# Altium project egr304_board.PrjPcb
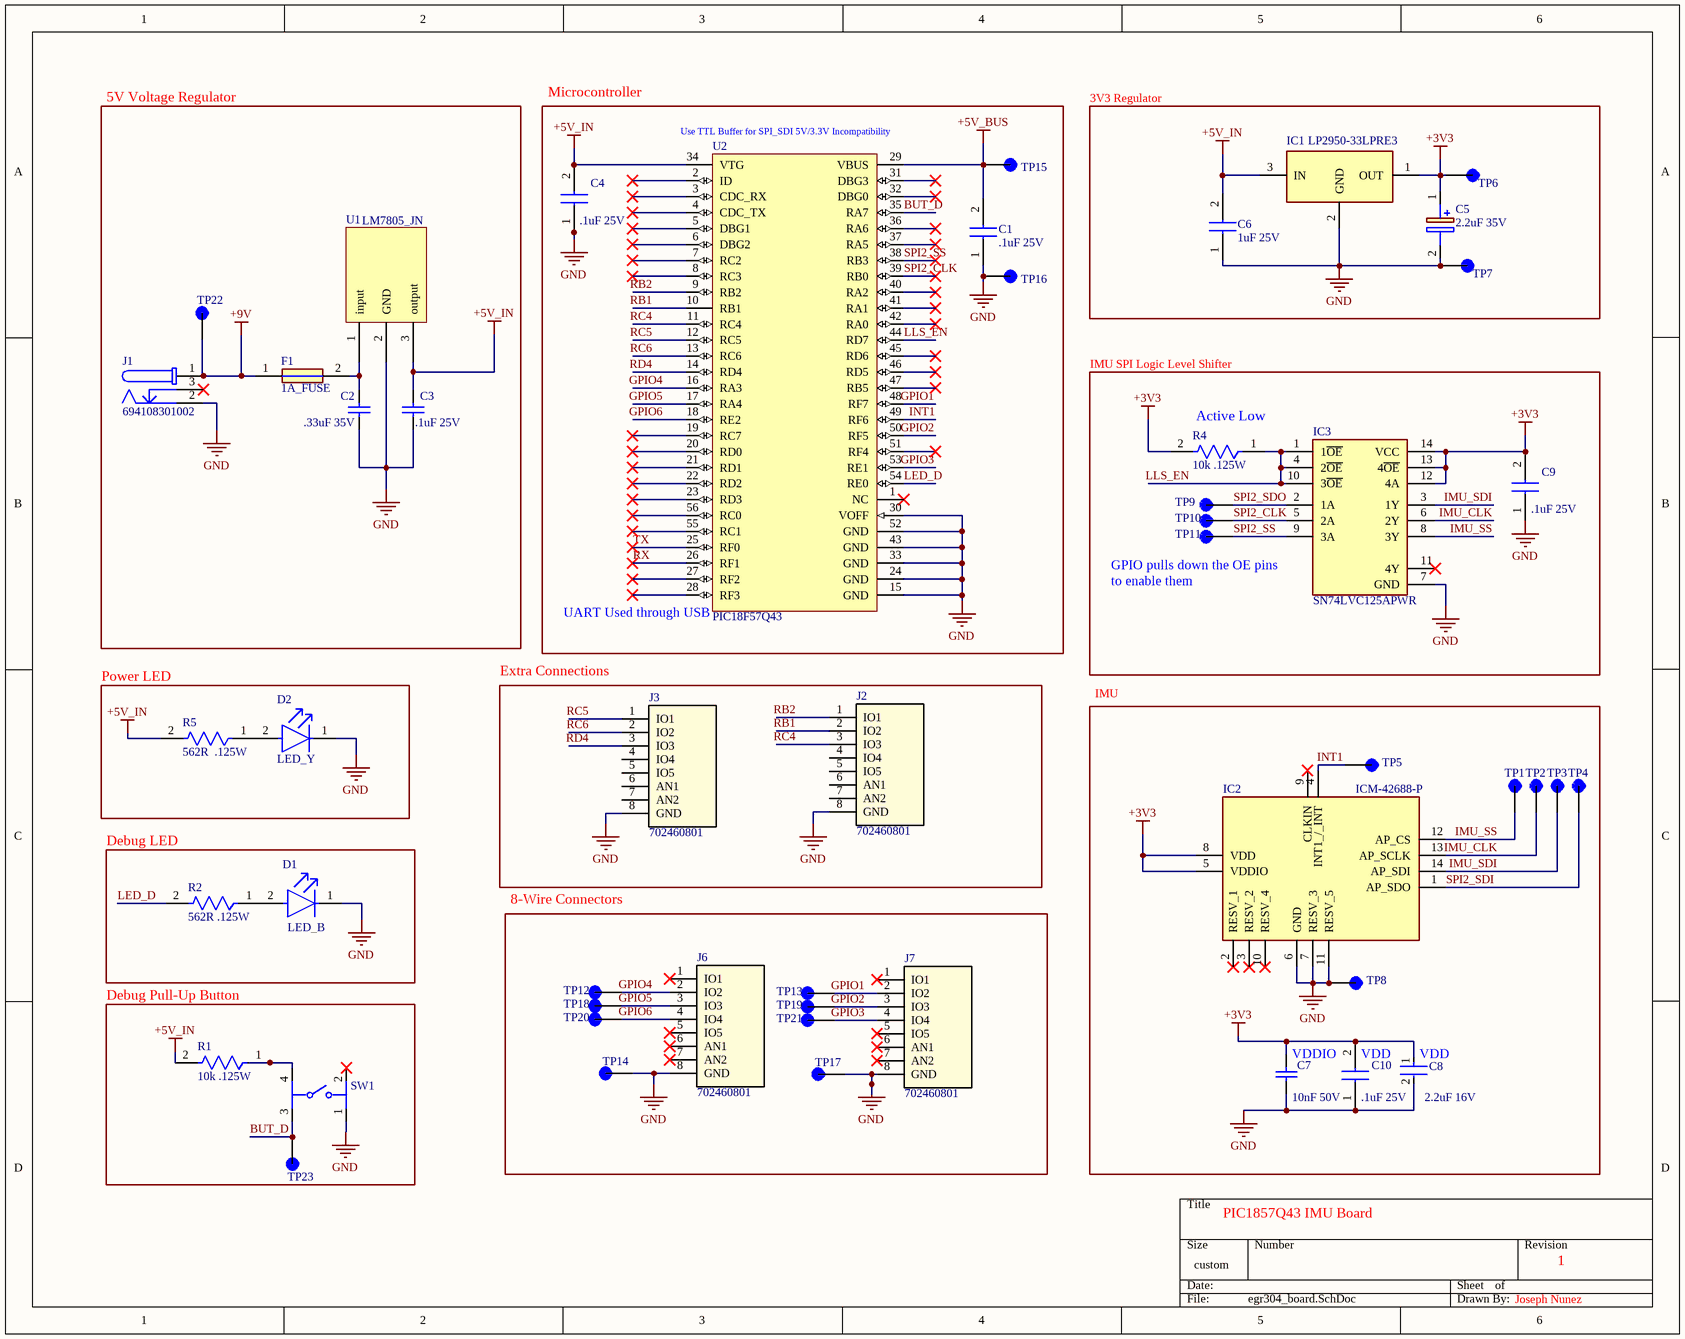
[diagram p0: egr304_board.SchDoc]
1 sheet, 51 parts. Net scope: global (net labels, ports and power ports of the same name join across sheets).
Board file: PCB1.PcbDoc

## Sheet egr304_board.SchDoc
size 314 x 250 mm; SheetNumber: 1; SheetTotal: 1

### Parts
C1  .1uF 25V  [C2012_Commercial]
C2  .33uF 35V  [CAPC2113X120X50LL20T30]
C3  .1uF 25V  [CAPC1005X56X25NL10T15]
C4  .1uF 25V  [C2012_Commercial]
C5  2.2uF 35V  [CAPPM3216X180N]
C6  1uF 25V  [C2012_Commercial]
C7  10nF 50V  [CAPC2013X94X50ML20T25]
C8  2.2uF 16V  [FP-C0805C225K4RACAUTO-MFG]
C9  .1uF 25V  [C2012_Commercial]
C10  .1uF 25V  [C2012_Commercial]
D1  LED_B  [FP-SML-D12-MFG]
D2  LED_Y  [FP-SML-D12-MFG]
F1  1A_FUSE  [FUSC1608X61N]
IC1  LP2950-33LPRE3  [TL431CLPM]
IC2  ICM-42688-P  [IIM42352]
IC3  SN74LVC125APWR  [SN74LVC125APWR]
J1  694108301002  [694108301002]
J2  702460801  [CONN_7024608xx_MOL]
J3  702460801  [CONN_7024608xx_MOL]
J6  702460801  [CONN_7024608xx_MOL]
J7  702460801  [CONN_7024608xx_MOL]
R1  10k .125W  [FP-CRGCQ0805-IPC_C]
R2  562R .125W  [FP-RT0805-MFG]
R4  10k .125W  [FP-CRGCQ0805-IPC_C]
R5  562R  .125W  [FP-RT0805-MFG]
SW1  Button  [FP-1301_9320-MFG]  (value not drawn)
TP1  5001  [KEYSTONE_5001]  (value not drawn)
TP2  5001  [KEYSTONE_5001]  (value not drawn)
TP3  5001  [KEYSTONE_5001]  (value not drawn)
TP4  5001  [KEYSTONE_5001]  (value not drawn)
TP5  5001  [KEYSTONE_5001]  (value not drawn)
TP6  5001  [KEYSTONE_5001]  (value not drawn)
TP7  5001  [KEYSTONE_5001]  (value not drawn)
TP8  5001  [KEYSTONE_5001]  (value not drawn)
TP9  5001  [KEYSTONE_5001]  (value not drawn)
TP10  5001  [KEYSTONE_5001]  (value not drawn)
TP11  5001  [KEYSTONE_5001]  (value not drawn)
TP12  5001  [KEYSTONE_5001]  (value not drawn)
TP13  5001  [KEYSTONE_5001]  (value not drawn)
TP14  5001  [KEYSTONE_5001]  (value not drawn)
TP15  5001  [KEYSTONE_5001]  (value not drawn)
TP16  5001  [KEYSTONE_5001]  (value not drawn)
TP17  5001  [KEYSTONE_5001]  (value not drawn)
TP18  5001  [KEYSTONE_5001]  (value not drawn)
TP19  5001  [KEYSTONE_5001]  (value not drawn)
TP20  5001  [KEYSTONE_5001]  (value not drawn)
TP21  5001  [KEYSTONE_5001]  (value not drawn)
TP22  5001  [KEYSTONE_5001]  (value not drawn)
TP23  5001  [KEYSTONE_5001]  (value not drawn)
U1  LM7805_JN  [LM7805_JN]
U2  PIC18F57Q43  [PIC1857Q43_JN]

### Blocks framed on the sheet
5V Voltage Regulator: C2 C3 F1 J1 TP22 U1
Microcontroller: C1 C4 TP15 TP16 U2
3V3 Regulator: C5 C6 IC1 TP6 TP7
Active Low: C9 IC3 R4 TP9-TP11
Power LED: D2 R5
Extra Connections: J2 J3
Debug LED: D1 R2
8-Wire Connectors: J6 J7 TP12-TP14 TP17-TP21
Debug Pull-Up Button: R1 SW1 TP23

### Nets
+3V3: C5.1(+) C7.2 C8.1 C9.2 C10.2 IC1.1(OUT) IC2.5(VDDIO) IC2.8(VDD) IC3.12(4A) IC3.13(4~{OE}) IC3.14(VCC) R4.2 TP6.TP
+5V_BUS: C1.2 TP15.TP U2.29(VBUS)
+5V_IN: C3.2 C4.2 C6.2 IC1.3(IN) R1.2 R5.2 U1.3(output) U2.34(VTG)
+9V: F1.1 J1.1 TP22.TP
GND: C1.1 C2.1 C3.1 C4.1 C5.2(-) C6.1 C7.1 C8.2 C9.1 C10.1 D1.1(C) D2.1(C) IC1.2(GND) IC2.6(GND) IC2.7(RESV_3) IC2.11(RESV_5) IC3.7(GND) J1.2 J2.8(GND) J3.8(GND) J6.8(GND) J7.8(GND) SW1.1 TP7.TP TP8.TP TP14.TP TP16.TP TP17.TP U1.2(GND) U2.15(GND) U2.24(GND) U2.30(VOFF) U2.33(GND) U2.43(GND) U2.52(GND)
BUT_D: SW1.3 TP23.TP U2.35(RA7)
GPIO1: J7.2(IO2) TP13.TP U2.48(RF7)
GPIO2: J7.3(IO3) TP19.TP U2.50(RF5)
GPIO3: J7.4(IO4) TP21.TP U2.53(RE1)
GPIO4: J6.2(IO2) TP12.TP U2.16(RA3)
GPIO5: J6.3(IO3) TP18.TP U2.17(RA4)
GPIO6: J6.4(IO4) TP20.TP U2.18(RE2)
IMU_CLK: IC2.13(AP_SCLK) IC3.6(2Y) TP2.TP
IMU_SDI: IC2.14(AP_SDI) IC3.3(1Y) TP3.TP
IMU_SS: IC2.12(AP_CS) IC3.8(3Y) TP1.TP
INT1: IC2.4(INT1_/_INT) TP5.TP U2.49(RF6)
LED_D: R2.2 U2.54(RE0)
LLS_EN: IC3.1(1~{OE}) IC3.4(2~{OE}) IC3.10(3~{OE}) R4.1 U2.44(RD7)
RB1: J2.2(IO2) U2.10(RB1)
RB2: J2.1(IO1) U2.9(RB2)
RC4: J2.3(IO3) U2.11(RC4)
RC5: J3.1(IO1) U2.12(RC5)
RC6: J3.2(IO2) U2.13(RC6)
RD4: J3.3(IO3) U2.14(RD4)
RX: U2.26(RF1)
SPI2_CLK: IC3.5(2A) TP10.TP U2.39(RB0)
SPI2_SDI: IC2.1(AP_SDO) TP4.TP
SPI2_SDO: IC3.2(1A) TP9.TP
SPI2_SS: IC3.9(3A) TP11.TP U2.38(RB3)
TX: U2.25(RF0)
NetC2_2: C2.2 F1.2 U1.1(input)
NetD1_2: D1.2(A) R2.1
NetD2_2: D2.2(A) R5.1
NetR1_1: R1.1 SW1.4

Not connected (* = marked no-connect by the designer): IC2 2(RESV_1)* 3(RESV_2)* 9(CLKIN)* 10(RESV_4)*; IC3 11(4Y)*; J1 3*; J2 4(IO4) 5(IO5) 6(AN1) 7(AN2); J3 4(IO4) 5(IO5) 6(AN1) 7(AN2); J6 1(IO1)* 5(IO5)* 6(AN1)* 7(AN2)*; J7 1(IO1)* 5(IO5)* 6(AN1)* 7(AN2)*; SW1 2*; U2 1(NC)* 2(ID)* 3(CDC_RX)* 4(CDC_TX)* 5(DBG1)* 6(DBG2)* 7(RC2)* 8(RC3)* 19(RC7)* 20(RD0)* 21(RD1)* 22(RD2)* 23(RD3)* 27(RF2)* 28(RF3)* 31(DBG3)* 32(DBG0)* 36(RA6)* 37(RA5)* 40(RA2)* 41(RA1)* 42(RA0)* 45(RD6)* 46(RD5)* 47(RB5)* 51(RF4)* 55(RC1)* 56(RC0)*

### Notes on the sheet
- (near U2) Use TTL Buffer for SPI_SDI 5V/3.3V Incompatibility
- IMU SPI Logic Level Shifter
- (near U2) UART Used through USB
- GPIO pulls down the OE pins
- to enable them
- IMU
- (near C7) VDDIO
- (near C10) VDD
- (near C8) VDD
- PIC1857Q43 IMU Board
- 1
- Joseph Nunez

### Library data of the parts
C1 C4 C9 C10 = C2012X7R1V105K085AB: Capacitor / C0805C104J3RACTU / 0805; Manufacturer_Name: TDK
C2 = CMP-2007-04070-1: TAJR334K035RNJ; Manufacturer: AVX Interconnect / Elco
C3 = CMP-1034-02072-2: 04023D104KAT2A; Manufacturer: AVX Interconnect / Elco
C5 = TPSA225K035R1500: Capacitor Polarised / 1.5ohm ESR for Output Requirement / Tantalum / 1206; Manufacturer_Name: Kyocera AVX
C6 = C2012X7R1V105K085AB: Capacitor / C0805C105K3RACTU / 0805; Manufacturer_Name: TDK
C7 = CMP-2007-04453-1: KGM21NR71H103KT / 0805; Manufacturer: AVX Interconnect / Elco; Part Number: 0805YC103MAT2A
C8 = CMP-2007-03267-2: CAP CER 2.2UF 16V X7R 0805 / C0805C225K4RACAUTO; Tolerance: 10%; Dielectric Material: Ceramic
D1 = CMP-08952-000023-1: SMLD12BN1WT86 / BLUE LED 0603; Manufacturer: Rohm; Manufacturer Part Number: SML-D12Y8WT86; Forward Voltage: 2.2V; Wavelength: 590nm; Reverse Voltage: 5V; Led Orientation: Top View; Forward Current: 20mA; Colour: Yellow; Power Dissipation: 54mW; Luminous Intensity: 63mcd
D2 = CMP-08952-000023-1: LED YELLOW DIFFUSED 0603 SMD / SML-D12Y8WT86; Manufacturer: Rohm; Forward Voltage: 2.2V; Wavelength: 590nm; Reverse Voltage: 5V; Led Orientation: Top View; Forward Current: 20mA; Power Dissipation: 54mW; Luminous Intensity: 63mcd
F1 = 0438001.A: Fuse; Manufacturer_Name: LITTELFUSE
IC1 = LP2950-33LPRE3: Integrated Circuit; Manufacturer_Name: Texas Instruments
IC2 = ICM-42688-P: Integrated Circuit; Manufacturer_Name: TDK
IC3 = SN74LVC125APWR: Integrated Circuit; Manufacturer_Name: Texas Instruments
J1 = CMP-1502-00190-4: DC Power Jack Connector WR-DC, Male, Right Angled, THT, 5 A, 24 V; Operating Supply Voltage: 24V; Shielding: Unshielded; Voltage Rating: 30V; Number of Contacts: 3; Insulation Resistance: 100MΩ; Current Rating: 5A
J2 J3 J6 J7 = 702460801: 2.54mm Pitch C-Grid Header, Low Profile, Dual Row, Vertical, Shrouded, 8  Circuits, 0.38Âµm Gold (Au) Selective Plating; Manufacturer_Name: Molex Connector Corporation
R1 R4 = CMP-03211-002989-1: CRGCQ0805J10K; Manufacturer: TE Connectivity; Voltage Rating: 150V; Temperature Coefficient: ±100ppm/°C; Resistance: 10KΩ; Value: 10KΩ; Power Rating: 0.125W; Tolerance: 0.05; Automotive Grade: Grade 914
R2 R5 = CMP-03412-035770-1: RES SMD 562 OHM 1% 1/8W 0805 / RT0805FRD07562RL; Manufacturer: Yageo; Tolerance: 0.0001; Temperature Coefficient: 25 ppm/°C; Resistance: 562Ω; Power Rating: 0.125W; Voltage Rating: 150V; Value: 562Ω
SW1 = CMP-26321-000001-1: SWITCH TACTILE SPST-NO 0.05A 12V / 1301.9320; Manufacturer: Schurter; Electromechanical Life: 100000Cycles; Contact Current Rating: 50mA; Contact Resistance: 100mΩ; Operating Force: 1.6N
TP1-TP23 = CMP-003-000000-1: MF: Keystone Electronics
U1 = LM7805_JN_1
U2 = PIC18F57Q43_JN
